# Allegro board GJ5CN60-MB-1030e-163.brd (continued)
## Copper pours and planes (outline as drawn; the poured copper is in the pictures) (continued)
NVVDD on TOP (solid shape): 83.1,104.32 83.16,104.41 83.27,104.39 83.4,104.26 83.87,104.26 83.87,103.95 83.72,103.8 83.72,103.76 83.64,103.68 83.64,103.38 83.72,103.31 83.72,103.28 83.75,103.21 83.92,103.04 83.92,102.62 83.75,102.46 83.72,102.38 83.72,102.36 83.62,102.25 83.62,102.01 83.72,101.91 83.72,101.88 83.75,101.81 83.89,101.66 83.89,101.22 83.75,101.08 83.74,101.04 83.72,100.98 83.68,100.93 83.64,100.9 83.64,100.83 83.63,100.78 83.63,100.73 83.6,100.66 83.53,100.63 83.42,100.6 83.33,100.52 83.29,100.51 83.21,100.5 83.16,100.48 83.1,100.48 83.1,100.54 83.06,100.57 82.98,100.71 82.98,100.87 83.05,100.93 83.1,101.03 83.1,101.89 83.06,101.92 82.97,102.13 83.06,102.34 83.1,102.37 83.1,103.29 83.06,103.32 82.97,103.53 83.06,103.74 83.1,103.77
NVVDD on TOP (solid shape): 83.1,104.32 83.16,104.41 83.27,104.39 83.4,104.26 83.87,104.26 83.87,103.95 83.72,103.8 83.72,103.76 83.64,103.68 83.64,103.38 83.72,103.31 83.72,103.28 83.75,103.21 83.92,103.04 83.92,102.62 83.75,102.46 83.72,102.38 83.72,102.36 83.62,102.25 83.62,102.01 83.72,101.91 83.72,101.88 83.75,101.81 83.89,101.66 83.89,101.22 83.75,101.08 83.74,101.04 83.72,100.98 83.68,100.93 83.64,100.9 83.64,100.83 83.63,100.78 83.63,100.73 83.6,100.66 83.53,100.63 83.42,100.6 83.33,100.52 83.29,100.51 83.21,100.5 83.16,100.48 83.1,100.48 83.1,100.54 83.06,100.57 82.98,100.71 82.98,100.87 83.05,100.93 83.1,101.03 83.1,101.89 83.06,101.92 82.97,102.13 83.06,102.34 83.1,102.37 83.1,103.29 83.06,103.32 82.97,103.53 83.06,103.74 83.1,103.77
NVVDD on TOP (solid shape): 83.1,104.32 83.16,104.41 83.27,104.39 83.4,104.26 83.87,104.26 83.87,103.95 83.72,103.8 83.72,103.76 83.64,103.68 83.64,103.38 83.72,103.31 83.72,103.28 83.75,103.21 83.92,103.04 83.92,102.62 83.75,102.46 83.72,102.38 83.72,102.36 83.62,102.25 83.62,102.01 83.72,101.91 83.72,101.88 83.75,101.81 83.89,101.66 83.89,101.22 83.75,101.08 83.74,101.04 83.72,100.98 83.68,100.93 83.64,100.9 83.64,100.83 83.63,100.78 83.63,100.73 83.6,100.66 83.53,100.63 83.42,100.6 83.33,100.52 83.29,100.51 83.21,100.5 83.16,100.48 83.1,100.48 83.1,100.54 83.06,100.57 82.98,100.71 82.98,100.87 83.05,100.93 83.1,101.03 83.1,101.89 83.06,101.92 82.97,102.13 83.06,102.34 83.1,102.37 83.1,103.29 83.06,103.32 82.97,103.53 83.06,103.74 83.1,103.77
NVVDD on TOP (solid shape): 73.36,104.3 73.41,104.31 73.44,104.26 73.44,103.8 73.49,103.76 73.62,103.53 73.49,103.3 73.44,103.27 73.44,102.4 73.49,102.36 73.62,102.13 73.49,101.9 73.44,101.87 73.44,101.09 73.5,101.04 73.5,101.02 73.54,100.93 73.62,100.86 73.62,100.78 73.62,100.65 73.47,100.5 73.34,100.5 73.3,100.51 73.26,100.52 73.17,100.6 73.05,100.63 73.01,100.65 73,100.68 73,100.85 72.93,100.92 72.88,100.97 72.77,101.07 72.77,101.76 72.87,101.86 72.87,101.9 72.9,101.94 72.96,102 73,102.07 73,102.19 72.96,102.26 72.9,102.32 72.87,102.36 72.87,102.38 72.84,102.48 72.8,102.52 72.8,103.16 72.84,103.21 72.87,103.28 72.87,103.3 72.92,103.36 72.93,103.39 72.96,103.53 72.93,103.68 72.92,103.7 72.87,103.76 72.87,103.8 72.77,103.9 72.77,104.24 73.3,104.24
NVVDD on TOP (solid shape): 86.01,96.76 86.09,96.76 86.13,96.74 86.22,96.67 86.33,96.63 86.39,96.6 86.42,96.53 86.42,96.39 86.49,96.32 86.51,96.29 86.59,96.21 86.59,95.45 86.52,95.38 86.52,95.36 86.42,95.25 86.42,95.01 86.52,94.9 86.52,94.88 86.54,94.75 86.54,94.11 86.55,94.07 86.54,94.03 86.52,93.98 86.52,93.96 86.49,93.92 86.42,93.85 86.42,93.61 86.49,93.54 86.52,93.51 86.52,93.46 86.57,93.41 86.57,92.99 86.2,92.99 86.07,92.86 85.96,92.84 85.9,92.93 85.9,93.5 85.86,93.53 85.77,93.73 85.86,93.94 85.9,93.97 85.9,94.9 85.86,94.93 85.77,95.13 85.86,95.34 85.9,95.37 85.9,96.24 85.88,96.26 85.84,96.34 85.78,96.39 85.78,96.55 85.86,96.69 85.9,96.72 85.9,96.78 85.96,96.78
NVVDD on TOP (solid shape): 86.01,96.76 86.09,96.76 86.13,96.74 86.22,96.67 86.33,96.63 86.39,96.6 86.42,96.54 86.42,96.39 86.49,96.32 86.51,96.29 86.59,96.21 86.59,95.45 86.52,95.38 86.52,95.36 86.42,95.25 86.42,95.01 86.52,94.9 86.52,94.88 86.54,94.75 86.54,94.11 86.55,94.1 86.55,94.07 86.54,94.03 86.52,93.98 86.52,93.96 86.42,93.85 86.42,93.61 86.52,93.5 86.52,93.46 86.57,93.41 86.57,92.99 86.2,92.99 86.07,92.86 85.96,92.84 85.9,92.93 85.9,93.5 85.86,93.53 85.77,93.73 85.86,93.94 85.9,93.97 85.9,94.9 85.86,94.93 85.77,95.13 85.86,95.34 85.9,95.37 85.9,96.24 85.88,96.26 85.84,96.34 85.78,96.39 85.78,96.55 85.86,96.69 85.9,96.72 85.9,96.78 85.96,96.78
NVVDD on TOP (solid shape): 73.36,104.3 73.41,104.31 73.44,104.26 73.44,103.8 73.49,103.76 73.62,103.53 73.49,103.3 73.44,103.27 73.44,102.4 73.49,102.36 73.62,102.13 73.49,101.9 73.44,101.87 73.44,101.09 73.5,101.04 73.5,101.02 73.54,100.93 73.62,100.86 73.62,100.78 73.62,100.65 73.47,100.5 73.34,100.5 73.3,100.51 73.26,100.52 73.17,100.6 73.05,100.63 73.01,100.65 73,100.68 73,100.85 72.93,100.92 72.88,100.97 72.77,101.07 72.77,101.76 72.87,101.86 72.87,101.9 72.96,102 73,102.07 73,102.19 72.96,102.26 72.87,102.36 72.87,102.38 72.84,102.48 72.8,102.52 72.8,103.16 72.84,103.21 72.87,103.28 72.87,103.3 72.92,103.36 72.93,103.39 72.96,103.53 72.93,103.68 72.92,103.7 72.87,103.76 72.87,103.8 72.77,103.9 72.77,104.24 73.3,104.24
NVVDD on TOP (solid shape): 73.36,104.3 73.41,104.31 73.44,104.26 73.44,103.8 73.49,103.76 73.62,103.53 73.49,103.3 73.44,103.27 73.44,102.4 73.49,102.36 73.62,102.13 73.49,101.9 73.44,101.87 73.44,101.09 73.5,101.04 73.5,101.02 73.54,100.93 73.62,100.86 73.62,100.78 73.62,100.65 73.47,100.5 73.34,100.5 73.3,100.51 73.26,100.52 73.17,100.6 73.05,100.63 73.01,100.65 73,100.68 73,100.85 72.93,100.92 72.88,100.97 72.77,101.07 72.77,101.76 72.87,101.86 72.87,101.9 72.96,102 73,102.07 73,102.19 72.96,102.26 72.87,102.36 72.87,102.38 72.84,102.48 72.8,102.52 72.8,103.16 72.84,103.21 72.87,103.28 72.87,103.3 72.92,103.36 72.93,103.39 72.96,103.53 72.93,103.68 72.92,103.7 72.87,103.76 72.87,103.8 72.77,103.9 72.77,104.24 73.3,104.24
NVVDD on TOP (solid shape): 83.21,96.76 83.29,96.76 83.33,96.74 83.42,96.67 83.53,96.63 83.59,96.6 83.62,96.54 83.62,96.39 83.69,96.32 83.71,96.29 83.79,96.21 83.79,95.45 83.72,95.38 83.72,95.36 83.62,95.25 83.62,95.01 83.72,94.9 83.72,94.88 83.74,94.75 83.74,94.11 83.75,94.1 83.75,94.07 83.72,93.98 83.72,93.96 83.62,93.85 83.62,93.61 83.72,93.5 83.72,93.46 83.77,93.41 83.77,93.01 83.41,93.01 83.27,92.87 83.16,92.85 83.1,92.94 83.1,93.5 83.06,93.53 82.97,93.73 83.06,93.94 83.1,93.97 83.1,94.9 83.06,94.93 82.97,95.13 83.06,95.34 83.1,95.37 83.1,96.24 83.08,96.26 83.04,96.34 82.98,96.39 82.98,96.55 83.06,96.69 83.1,96.72 83.1,96.78 83.16,96.78
NVVDD on TOP (solid shape): 83.21,96.76 83.29,96.76 83.33,96.74 83.42,96.67 83.53,96.63 83.59,96.6 83.62,96.53 83.62,96.39 83.69,96.32 83.71,96.29 83.79,96.21 83.79,95.45 83.72,95.38 83.72,95.36 83.62,95.25 83.62,95.01 83.72,94.9 83.72,94.88 83.74,94.75 83.74,94.11 83.75,94.1 83.75,94.07 83.72,93.98 83.72,93.96 83.62,93.85 83.62,93.61 83.72,93.5 83.72,93.46 83.77,93.41 83.77,93.01 83.41,93.01 83.27,92.87 83.16,92.85 83.1,92.94 83.1,93.5 83.06,93.53 82.97,93.73 83.06,93.94 83.1,93.97 83.1,94.9 83.06,94.93 82.97,95.13 83.06,95.34 83.1,95.37 83.1,96.24 83.08,96.26 83.04,96.34 82.98,96.39 82.98,96.55 83.06,96.69 83.1,96.72 83.1,96.78 83.16,96.78
NVVDD on TOP (solid shape): 86.01,96.76 86.09,96.76 86.13,96.74 86.22,96.67 86.33,96.63 86.39,96.6 86.42,96.53 86.42,96.39 86.49,96.32 86.51,96.29 86.59,96.21 86.59,95.45 86.52,95.38 86.52,95.36 86.42,95.25 86.42,95.01 86.52,94.9 86.52,94.88 86.54,94.75 86.54,94.11 86.55,94.07 86.54,94.03 86.52,93.98 86.52,93.96 86.42,93.85 86.42,93.61 86.52,93.51 86.52,93.46 86.57,93.41 86.57,92.99 86.2,92.99 86.07,92.86 85.96,92.84 85.9,92.93 85.9,93.5 85.86,93.53 85.77,93.73 85.86,93.94 85.9,93.97 85.9,94.9 85.86,94.93 85.77,95.13 85.86,95.34 85.9,95.37 85.9,96.24 85.88,96.26 85.84,96.34 85.78,96.39 85.78,96.55 85.86,96.69 85.9,96.72 85.9,96.78 85.96,96.78
NVVDD on TOP (solid shape): 76.16,104.29 76.21,104.3 76.24,104.25 76.24,103.8 76.29,103.76 76.42,103.53 76.29,103.3 76.24,103.27 76.24,102.4 76.29,102.36 76.42,102.13 76.29,101.9 76.24,101.87 76.24,101.05 76.3,101.01 76.31,100.99 76.35,100.92 76.41,100.87 76.41,100.69 76.29,100.55 76.22,100.5 76.14,100.5 76.1,100.51 76.06,100.52 75.97,100.6 75.85,100.63 75.81,100.65 75.8,100.68 75.8,100.85 75.73,100.92 75.68,100.97 75.57,101.07 75.57,101.76 75.67,101.86 75.67,101.9 75.7,101.94 75.76,102 75.8,102.07 75.8,102.19 75.76,102.26 75.7,102.32 75.67,102.36 75.67,102.38 75.64,102.48 75.6,102.52 75.6,103.16 75.64,103.21 75.67,103.28 75.67,103.3 75.72,103.36 75.73,103.39 75.76,103.53 75.73,103.68 75.72,103.7 75.67,103.76 75.67,103.8 75.57,103.9 75.57,104.24 76.11,104.24
NVVDD on TOP (solid shape): 76.16,104.29 76.21,104.3 76.24,104.25 76.24,103.8 76.29,103.76 76.42,103.53 76.29,103.3 76.24,103.27 76.24,102.4 76.29,102.36 76.42,102.13 76.29,101.9 76.24,101.87 76.24,101.05 76.3,101.01 76.31,100.99 76.35,100.92 76.41,100.87 76.41,100.69 76.29,100.55 76.22,100.5 76.14,100.5 76.1,100.51 76.06,100.52 75.97,100.6 75.85,100.63 75.81,100.65 75.8,100.68 75.8,100.85 75.73,100.92 75.68,100.97 75.57,101.07 75.57,101.76 75.67,101.86 75.67,101.9 75.76,102 75.8,102.07 75.8,102.19 75.76,102.26 75.7,102.32 75.67,102.36 75.67,102.38 75.64,102.48 75.6,102.52 75.6,103.16 75.64,103.21 75.67,103.28 75.67,103.3 75.72,103.36 75.73,103.39 75.76,103.53 75.73,103.68 75.72,103.7 75.67,103.76 75.67,103.8 75.57,103.9 75.57,104.24 76.11,104.24
NVVDD on TOP (solid shape): 76.16,104.29 76.21,104.3 76.24,104.25 76.24,103.8 76.29,103.76 76.42,103.53 76.29,103.3 76.24,103.27 76.24,102.4 76.29,102.36 76.42,102.13 76.29,101.9 76.24,101.87 76.24,101.05 76.3,101.01 76.31,100.99 76.35,100.92 76.41,100.87 76.41,100.69 76.29,100.55 76.22,100.5 76.14,100.5 76.1,100.51 76.06,100.52 75.97,100.6 75.85,100.63 75.81,100.65 75.8,100.68 75.8,100.85 75.73,100.92 75.68,100.97 75.57,101.07 75.57,101.76 75.67,101.86 75.67,101.9 75.7,101.94 75.76,102 75.8,102.07 75.8,102.19 75.76,102.26 75.67,102.36 75.67,102.38 75.64,102.48 75.6,102.52 75.6,103.16 75.64,103.21 75.67,103.28 75.67,103.3 75.72,103.36 75.73,103.39 75.76,103.53 75.73,103.68 75.72,103.7 75.67,103.76 75.67,103.8 75.57,103.9 75.57,104.24 76.11,104.24
NVVDD on TOP (solid shape): 70.56,104.46 70.61,104.47 70.64,104.42 70.64,103.8 70.69,103.76 70.82,103.53 70.69,103.3 70.64,103.27 70.64,102.4 70.69,102.36 70.82,102.13 70.69,101.9 70.64,101.87 70.64,101.05 70.7,101.01 70.71,100.99 70.75,100.92 70.81,100.87 70.81,100.69 70.69,100.55 70.61,100.5 70.52,100.51 70.49,100.51 70.46,100.52 70.37,100.6 70.25,100.63 70.21,100.65 70.2,100.68 70.2,100.85 70.13,100.91 70.08,100.96 69.97,101.07 69.97,101.76 70.07,101.86 70.07,101.9 70.1,101.94 70.16,102 70.2,102.07 70.2,102.19 70.16,102.26 70.07,102.36 70.07,102.38 70.04,102.48 70,102.52 70,103.16 70.04,103.21 70.07,103.28 70.07,103.3 70.12,103.36 70.13,103.39 70.16,103.53 70.13,103.68 70.12,103.7 70.07,103.76 70.07,103.8 69.97,103.9 69.97,104.26 70.46,104.26 70.54,104.34 70.54,104.44
NVVDD on TOP (solid shape): 85.9,104.23 85.96,104.32 86.07,104.3 86.13,104.24 86.55,104.24 86.58,104.27 86.64,104.28 86.67,104.24 86.67,103.95 86.52,103.8 86.52,103.76 86.44,103.68 86.44,103.63 86.44,103.62 86.43,103.53 86.44,103.44 86.44,103.43 86.44,103.38 86.52,103.31 86.52,103.28 86.55,103.21 86.72,103.04 86.72,102.62 86.55,102.46 86.52,102.38 86.52,102.36 86.42,102.25 86.42,102.01 86.52,101.91 86.52,101.88 86.55,101.81 86.69,101.66 86.69,101.22 86.55,101.08 86.52,100.98 86.48,100.93 86.44,100.9 86.44,100.83 86.43,100.78 86.43,100.73 86.4,100.66 86.33,100.63 86.22,100.6 86.13,100.52 86.09,100.51 86.01,100.5 85.96,100.48 85.9,100.48 85.9,100.54 85.86,100.57 85.78,100.71 85.78,100.87 85.85,100.93 85.9,101.03 85.9,101.89 85.86,101.92 85.77,102.13 85.86,102.34 85.9,102.37 85.9,103.29 85.86,103.32 85.77,103.53 85.86,103.74 85.9,103.77
NVVDD on TOP (solid shape): 85.9,104.23 85.96,104.32 86.07,104.3 86.13,104.24 86.55,104.24 86.58,104.27 86.64,104.28 86.67,104.24 86.67,103.95 86.52,103.8 86.52,103.76 86.44,103.68 86.43,103.53 86.44,103.38 86.52,103.31 86.52,103.28 86.55,103.21 86.72,103.04 86.72,102.62 86.55,102.46 86.52,102.38 86.52,102.36 86.42,102.25 86.42,102.01 86.52,101.91 86.52,101.88 86.55,101.81 86.69,101.66 86.69,101.22 86.55,101.08 86.52,100.98 86.48,100.93 86.44,100.9 86.44,100.83 86.43,100.78 86.43,100.73 86.4,100.66 86.33,100.63 86.22,100.6 86.13,100.52 86.09,100.51 86.01,100.5 85.96,100.48 85.9,100.48 85.9,100.54 85.86,100.57 85.78,100.71 85.78,100.87 85.85,100.93 85.9,101.03 85.9,101.89 85.86,101.92 85.77,102.13 85.86,102.34 85.9,102.37 85.9,103.29 85.86,103.32 85.77,103.53 85.86,103.74 85.9,103.77
NVVDD on TOP (solid shape): 85.9,104.23 85.96,104.32 86.07,104.3 86.13,104.24 86.55,104.24 86.58,104.27 86.64,104.28 86.67,104.24 86.67,103.95 86.52,103.8 86.52,103.76 86.44,103.68 86.43,103.53 86.44,103.38 86.52,103.31 86.52,103.28 86.55,103.21 86.72,103.04 86.72,102.62 86.55,102.46 86.52,102.38 86.52,102.36 86.42,102.25 86.42,102.01 86.52,101.91 86.52,101.88 86.55,101.81 86.69,101.66 86.69,101.22 86.55,101.08 86.52,100.98 86.48,100.93 86.44,100.9 86.44,100.83 86.43,100.78 86.43,100.73 86.4,100.66 86.33,100.63 86.22,100.6 86.13,100.52 86.09,100.51 86.01,100.5 85.96,100.48 85.9,100.48 85.9,100.54 85.86,100.57 85.78,100.71 85.78,100.87 85.85,100.93 85.9,101.03 85.9,101.89 85.86,101.92 85.77,102.13 85.86,102.34 85.9,102.37 85.9,103.29 85.86,103.32 85.77,103.53 85.86,103.74 85.9,103.77
NVVDD on TOP (solid shape): 70.56,104.46 70.61,104.47 70.64,104.42 70.64,103.8 70.69,103.76 70.82,103.53 70.69,103.3 70.64,103.27 70.64,102.4 70.69,102.36 70.82,102.13 70.69,101.9 70.64,101.87 70.64,101.05 70.7,101.01 70.71,100.99 70.75,100.92 70.81,100.87 70.81,100.69 70.69,100.55 70.61,100.5 70.52,100.51 70.49,100.51 70.46,100.52 70.37,100.6 70.25,100.63 70.21,100.65 70.2,100.68 70.2,100.85 70.13,100.91 70.08,100.96 69.97,101.07 69.97,101.76 70.07,101.86 70.07,101.9 70.16,102 70.2,102.07 70.2,102.19 70.16,102.26 70.07,102.36 70.07,102.38 70.04,102.48 70,102.52 70,103.16 70.04,103.21 70.07,103.28 70.07,103.3 70.12,103.36 70.13,103.39 70.16,103.53 70.13,103.68 70.12,103.7 70.07,103.76 70.07,103.8 69.97,103.9 69.97,104.26 70.46,104.26 70.54,104.34 70.54,104.44
NVVDD on TOP (solid shape): 76.24,96.78 76.24,96.75 76.29,96.72 76.41,96.58 76.41,96.39 76.35,96.34 76.31,96.27 76.3,96.25 76.24,96.22 76.24,95.37 76.28,95.34 76.32,95.3 76.36,95.22 76.37,95.21 76.37,95.13 76.37,95.05 76.36,95.04 76.32,94.96 76.27,94.92 76.22,94.87 76.22,94.69 76.28,94.65 76.33,94.59 76.37,94.49 76.36,94.34 76.28,94.22 76.24,94.19 76.24,93.97 76.28,93.94 76.37,93.73 76.28,93.52 76.24,93.49 76.24,93.24 76.39,93.09 76.39,92.97 76.32,92.9 76.19,93.02 75.68,93.02 75.66,93 75.6,92.99 75.57,93.04 75.57,93.36 75.65,93.44 75.69,93.51 75.73,93.55 75.77,93.58 75.77,93.89 75.73,93.92 75.69,93.95 75.65,94.02 75.5,94.17 75.5,94.66 75.64,94.81 75.68,94.9 75.73,94.95 75.77,94.98 75.77,95.29 75.73,95.32 75.68,95.36 75.64,95.46 75.57,95.52 75.57,96.11 75.64,96.18 75.65,96.22 75.68,96.3 75.75,96.36 75.8,96.39 75.8,96.58 75.81,96.61 75.85,96.63 75.97,96.66 76.06,96.74 76.14,96.76 76.18,96.8
NVVDD on TOP (solid shape): 76.24,96.78 76.24,96.75 76.29,96.72 76.41,96.58 76.41,96.39 76.35,96.34 76.31,96.27 76.3,96.25 76.24,96.22 76.24,95.37 76.28,95.34 76.32,95.3 76.36,95.22 76.37,95.21 76.37,95.13 76.37,95.05 76.36,95.04 76.32,94.96 76.27,94.92 76.22,94.87 76.22,94.69 76.28,94.65 76.33,94.59 76.37,94.49 76.36,94.34 76.28,94.22 76.24,94.19 76.24,93.97 76.28,93.94 76.37,93.73 76.28,93.52 76.24,93.49 76.24,93.24 76.39,93.09 76.39,92.97 76.32,92.9 76.19,93.02 75.68,93.02 75.66,93 75.6,92.99 75.57,93.04 75.57,93.36 75.65,93.44 75.69,93.51 75.73,93.55 75.77,93.58 75.77,93.89 75.73,93.92 75.69,93.95 75.65,94.02 75.5,94.17 75.5,94.66 75.64,94.81 75.68,94.9 75.73,94.95 75.77,94.98 75.77,95.29 75.73,95.32 75.68,95.36 75.64,95.46 75.57,95.52 75.57,96.11 75.64,96.18 75.65,96.22 75.68,96.3 75.75,96.36 75.8,96.39 75.8,96.58 75.81,96.61 75.85,96.63 75.97,96.66 76.06,96.74 76.14,96.76 76.18,96.8
NVVDD on TOP (solid shape): 76.24,96.78 76.24,96.75 76.29,96.72 76.34,96.68 76.38,96.63 76.42,96.51 76.41,96.39 76.35,96.34 76.31,96.27 76.3,96.25 76.24,96.22 76.24,95.37 76.28,95.34 76.32,95.3 76.36,95.22 76.37,95.21 76.37,95.13 76.37,95.05 76.36,95.04 76.32,94.96 76.27,94.92 76.22,94.87 76.22,94.69 76.28,94.65 76.33,94.59 76.37,94.49 76.36,94.34 76.28,94.22 76.24,94.19 76.24,93.97 76.28,93.94 76.37,93.73 76.28,93.52 76.24,93.49 76.24,93.24 76.39,93.09 76.39,92.97 76.32,92.9 76.19,93.02 75.68,93.02 75.66,93 75.6,92.99 75.57,93.04 75.57,93.36 75.65,93.44 75.69,93.51 75.73,93.55 75.77,93.58 75.77,93.89 75.73,93.92 75.69,93.95 75.65,94.02 75.5,94.17 75.5,94.66 75.64,94.81 75.68,94.9 75.73,94.95 75.77,94.98 75.77,95.29 75.73,95.32 75.68,95.36 75.64,95.46 75.57,95.52 75.57,96.11 75.64,96.18 75.65,96.22 75.68,96.3 75.75,96.36 75.8,96.39 75.8,96.58 75.81,96.61 75.85,96.63 75.97,96.66 76.06,96.74 76.14,96.76 76.18,96.8
NVVDD on BOTTOM (solid shape): 41.6,150.37 41.6,131.19 40.01,129.59 32.23,129.59 30.68,131.14 30.68,150.85 31.57,151.74 40.23,151.74
NVVDD on L6_IN2 (solid shape): 44.12,157.66 44.12,151.31 41.99,149.18 41.99,133.07 41.22,132.31 30.63,132.31 29.82,133.12 29.82,153.24 30.55,153.24 30.56,153.19 30.57,153.13 30.59,153.08 30.62,153.03 30.65,152.99 30.69,152.95 30.74,152.91 30.79,152.89 30.84,152.87 30.89,152.86 30.95,152.86 31.01,152.87 31.06,152.88 31.11,152.9 31.16,152.93 31.2,152.97 31.24,153.01 31.27,153.05 31.29,153.1 31.31,153.16 31.32,153.21 31.32,153.27 31.31,153.32 31.29,153.38 31.27,153.43 31.24,153.47 31.2,153.52 31.16,153.55 31.11,153.58 31.06,153.6 31.01,153.62 30.95,153.62 30.89,153.62 30.84,153.61 30.79,153.59 30.74,153.57 30.69,153.54 30.65,153.5 30.62,153.45 30.59,153.4 30.57,153.35 30.56,153.3 30.55,153.24 29.82,153.24 29.82,154.49 33.55,158.22 43.56,158.22
NVVDD on TOP: outline of 282 points within 25.35,88.54 113.23,158.96
NVVDD on BOTTOM: 86.38,96.68 86.38,96.4 86.66,96.12 86.66,95.58 86.38,95.3 86.38,95 86.66,94.72 86.66,94.19 86.38,93.91 86.38,93.6 86.66,93.32 86.66,92.76 86.6,92.7 86.14,92.7 85.93,92.92 85.93,93.42 85.83,93.53 85.83,96.68 85.93,96.78 86.28,96.78
NVVDD on BOTTOM: 70.2,100.71 70.2,100.92 70,101.12 70,101.76 70.2,101.96 70.2,103.56 69.93,103.84 69.93,104.47 69.95,104.5 70.56,104.5 70.69,104.37 70.69,103.84 70.81,103.71 70.81,103.33 70.69,103.2 70.69,102.5 70.84,102.34 70.84,102.06 70.69,101.91 70.69,101.17 70.84,101.02 70.84,100.64 70.71,100.51 70.41,100.51
NVVDD on BOTTOM: 76.28,100.41 75.89,100.41 75.64,100.66 75.64,104.47 75.77,104.6 76.28,104.6 76.4,104.47 76.4,100.54
NVVDD on BOTTOM: 77.16,106.99 77.35,107.18 77.35,107.28 77.98,107.28 78.06,107.23 78.07,107.14 78.06,106.99 78.12,106.85 78.12,106.51 78.12,106.5 78.08,106.29 78.18,106.11 78.19,106.1 78.19,105.98 78.14,105.98 78.14,105.87 77.95,105.87 77.95,105.98 77.25,105.98 77.25,106.29 77.16,106.37 77.16,106.39 77.14,106.46 77.1,106.53 77.1,106.84 77.14,106.9
NVVDD on BOTTOM: 84.45,97.54 84.78,97.54 85.04,97.28 85.04,90.63 84.91,90.5 84.91,89.36 84.78,89.23 84.4,89.23 84.28,89.36 84.28,90.88 84.66,91.27 84.66,92.03 84.4,92.28 84.4,97.49
NVVDD on BOTTOM: 68.14,103.08 68.65,103.08 68.77,102.96 68.77,102.45 68.87,102.35 69.23,102.35 69.36,102.22 69.36,102.07 69.23,101.94 68.79,101.94 68.66,101.81 68.66,101.32 68.54,101.21 68.06,101.21 68.05,101.22 68.05,102.99
NVVDD on BOTTOM: outline of 392 points within 70.05,89.11 108.61,130.56 ; 2 cut-outs
NVVDD on L2_GND1: 99.75,24.84 97.74,26.85 97.74,32.49 99.14,33.88 99.14,40.82 97.84,42.12 88.06,42.12 87.32,42.86 87.32,53.82 88.85,55.35 88.85,64.83 84.89,68.79 55.04,68.79 53.54,70.29 53.54,72.62 67.39,86.46 67.39,87.99 68.15,88.75 68.15,107.67 69.4,108.92 83.49,108.92 94.31,119.74 94.31,121.47 93.04,122.74 93.04,129.77 96.72,133.45 96.72,145.6 96.07,146.26 95.18,146.26 93.14,148.29 52.76,148.29 52,149.05 46.2,149.05 43.26,146.11 43.26,132.65 42.64,132.03 32.18,132.03 31.57,132.65 31.57,153.77 38.28,160.48 40.44,160.48 45.16,165.2 45.16,170.03 45.65,170.51 75.03,170.51 77.55,168 77.55,164.95 79.22,163.27 99.28,163.27 112.34,150.22 112.34,134.85 115.79,131.4 118.08,131.4 119.1,130.38 123.16,130.38 126.06,127.48 126.06,121.47 119.84,115.25 119.84,110.8 115.14,106.1 115.14,103.94 112.72,101.53 112.72,87.81 111.2,86.29 111.2,84.18 112.47,82.91 112.47,62.33 116.28,58.52 116.28,32.82 113.99,30.54 113.99,28.38 110.46,24.84
NVVDD on L3_IN1: outline of 163 points within 33.6,104.65 106.1,155.71
NVVDD on L4_VCC1: outline of 85 points within 32.21,24.84 126.06,170.64 ; 2 cut-outs
NVVDD on L5_VCC2: 72.19,67.39 69.52,70.06 53.77,70.06 52.27,71.56 52.27,77.83 55.04,80.6 61.65,80.6 67.26,86.21 67.26,108.43 68.76,109.93 70.31,109.93 70.31,109.39 70.41,109.29 71.34,109.29 71.65,109.61 71.65,109.93 80.85,109.93 80.85,109.28 81.03,109.1 81.72,109.1 81.89,109.27 81.89,109.93 86.54,109.93 95.71,119.1 95.71,145.09 94.03,146.76 48.36,146.76 45.16,143.57 45.16,128.58 43.28,126.7 36.12,126.7 27.13,135.69 27.13,152.46 27.04,152.55 27.54,153.05 27.54,153.12 27.52,153.14 26.45,153.14 25.48,154.11 25.48,162.79 33.33,170.64 76.68,170.64 80.16,167.16 90.55,167.16 90.83,166.88 90.83,159.13 92.17,157.79 99.82,157.79 106.5,151.1 106.5,147.24 110.69,143.05 110.69,113.47 106.63,109.4 106.63,96.96 95.35,85.68 90.27,85.68 88.34,83.75 88.34,75.42 80.31,67.39
NVVDD on L8_IN3: outline of 127 points within 32.71,88.52 104.09,153.11 ; 3 cut-outs
NVVDD_VIN on TOP (solid shape): 12.27,120.35 12.27,118.44 11.51,117.68 4.14,117.68 4.01,117.81 4.01,118.32 4.52,118.82 4.77,118.82 6.68,120.73 11.89,120.73
NVVDD_VIN on TOP (solid shape): outline of 197 points within 2.7,127.84 19.29,141.15
NVVDD_VIN on BOTTOM (solid shape): outline of 151 points within 3.43,129.52 18.44,140.69
NVVDD_VIN on TOP: 17.22,161.24 17.98,160.48 17.98,156.67 18.53,156.12 18.53,155.28 18.4,155.15 5.16,155.15 4.39,155.91 4.39,160.61 5.03,161.24
NVVDD_VIN on L5_VCC2: 1.47,117.68 1.47,140.18 5.54,144.25 5.54,148.27 1.73,152.08 1.73,160.5 3.86,162.64 24.71,162.64 24.97,162.38 24.97,153.9 26.62,152.25 26.62,135.48 35.72,126.38 28.65,119.31 28.65,117.68
NVVDD_VIN on L8_IN3: 5.79,160.86 14.3,160.86 17.86,157.31 17.86,122.38 13.16,117.68 4.52,117.68 4.27,117.94 4.27,118.44 6.43,120.6 6.43,125.43 4.01,127.84 4.01,139.53 4.65,140.16 6.55,140.16 8.2,141.81 8.2,144.61 7.57,145.24 7.57,151.34 4.77,154.13 4.77,159.85
NVVDDS on TOP (solid shape): 69.54,69.42 69.54,67.14 69.16,66.75 55.83,66.75 55.32,67.26 55.32,69.93 55.45,70.06 68.91,70.06
NVVDDS on TOP (solid shape): 70.65,92.9 70.57,92.82 70.57,91.87 70.67,91.77 70.67,91.57 70.57,91.47 70.57,90.47 70.69,90.34 70.69,90.2 70.59,90.1 70.59,89.98 70.26,89.64 70.06,89.64 69.97,89.73 69.97,89.76 70.22,90.02 70.22,90.42 70.08,90.57 70.08,90.62 70.22,90.77 70.22,91.15 70.05,91.32 70.05,91.97 70.22,92.14 70.22,92.55 70.03,92.75 70.03,92.94 70.11,93.02 70.53,93.02
NVVDDS on TOP (solid shape): 73.44,92.89 73.37,92.82 73.37,91.87 73.47,91.77 73.47,91.57 73.37,91.47 73.37,90.47 73.49,90.34 73.49,90.2 73.39,90.1 73.39,89.96 73.06,89.62 72.86,89.62 72.77,89.71 72.77,89.76 73.03,90.02 73.03,90.42 72.87,90.57 72.87,90.62 73.03,90.77 73.03,91.15 72.85,91.32 72.85,91.97 73.03,92.14 73.03,92.55 72.78,92.79 72.78,92.87 72.91,93 73.33,93
NVVDDS on TOP (solid shape): 76.21,92.86 76.17,92.82 76.17,91.87 76.27,91.77 76.27,91.57 76.17,91.47 76.17,90.47 76.29,90.34 76.29,90.2 76.19,90.1 76.19,89.86 75.88,89.54 75.68,89.54 75.59,89.63 75.59,89.78 75.83,90.02 75.83,90.42 75.67,90.57 75.67,90.62 75.83,90.77 75.83,91.15 75.65,91.32 75.65,91.97 75.83,92.14 75.83,92.55 75.62,92.75 75.62,92.82 75.73,92.92 76.15,92.92
NVVDDS on TOP (solid shape): 81,107.5 81,107.47 80.77,107.25 80.77,106.87 80.87,106.77 80.87,106.65 80.74,106.52 80.74,106.14 80.97,105.92 80.97,105.27 80.96,105.26 80.78,105.02 80.83,104.72 80.84,104.7 80.84,104.67 81.02,104.49 81.02,104.34 80.65,104.34 80.35,104.64 80.35,107.4 80.53,107.57 80.93,107.57
NVVDDS on TOP (solid shape): 83.8,107.52 83.8,107.47 83.57,107.25 83.57,106.87 83.67,106.77 83.67,106.65 83.54,106.52 83.54,106.14 83.77,105.92 83.77,105.27 83.76,105.26 83.58,105.02 83.63,104.72 83.64,104.7 83.64,104.67 83.82,104.49 83.82,104.36 83.45,104.36 83.15,104.66 83.15,107.42 83.33,107.59 83.73,107.59
NVVDDS on TOP (solid shape): 80.91,92.68 80.77,92.55 80.77,92.14 80.96,91.95 80.96,91.41 80.94,91.4 80.94,91.3 80.79,91.15 80.79,91.07 80.79,91.06 80.77,90.93 80.79,90.8 80.79,90.8 80.79,90.69 80.92,90.57 80.92,90.55 80.79,90.42 80.79,90.37 80.79,90.36 80.77,90.23 80.79,90.1 80.79,90.1 80.79,90.04 80.97,89.87 80.97,89.73 80.9,89.66 80.65,89.66 80.35,89.96 80.35,92.6 80.66,92.9 80.91,92.9
NVVDDS on TOP (solid shape): 83.71,92.68 83.57,92.55 83.57,92.14 83.76,91.95 83.76,91.41 83.74,91.4 83.74,91.3 83.59,91.15 83.59,91.07 83.59,91.06 83.57,90.93 83.59,90.8 83.59,90.8 83.59,90.69 83.72,90.57 83.72,90.55 83.59,90.42 83.59,90.37 83.59,90.36 83.57,90.23 83.59,90.1 83.59,90.1 83.59,90.04 83.77,89.87 83.77,89.74 83.7,89.67 83.45,89.67 83.15,89.97 83.15,92.61 83.46,92.91 83.71,92.91
NVVDDS on TOP (solid shape): 86.5,92.67 86.37,92.55 86.37,92.14 86.55,91.96 86.55,91.4 86.54,91.4 86.54,91.3 86.39,91.15 86.39,91.07 86.37,90.96 86.38,90.84 86.38,90.82 86.38,90.81 86.39,90.79 86.39,90.69 86.52,90.57 86.52,90.55 86.39,90.42 86.39,90.37 86.39,90.36 86.37,90.23 86.39,90.1 86.39,90.1 86.39,90.04 86.57,89.87 86.57,89.73 86.49,89.65 86.24,89.65 85.95,89.94 85.95,92.6 86.25,92.89 86.5,92.89
NVVDDS on TOP (solid shape): 86.78,107.94 86.82,107.88 86.88,107.83 86.9,107.81 86.9,107.74 86.86,107.74 86.37,107.25 86.37,106.87 86.47,106.77 86.47,106.65 86.34,106.52 86.34,106.14 86.57,105.92 86.57,105.27 86.56,105.26 86.38,105.02 86.43,104.72 86.44,104.7 86.44,104.67 86.61,104.5 86.61,104.44 86.51,104.34 86.18,104.34 85.95,104.57 85.95,106.65 85.99,106.68 85.99,107.76 86.2,107.97 86.76,107.97
NVVDDS on TOP (solid shape): 70.59,107.37 70.59,104.64 70.44,104.48 70.44,104.38 70.42,104.36 70.03,104.36 70.03,104.49 70.2,104.67 70.2,104.8 70.2,104.8 70.22,104.93 70.2,105.06 70.2,105.07 70.2,105.15 70,105.35 70,105.94 70.18,106.12 70.18,106.14 70.18,106.15 70.23,106.34 70.18,106.52 70.18,106.84 70.23,107.03 70.18,107.21 70.18,107.22 70.18,107.25 69.91,107.51 69.91,107.61 70.35,107.61
NVVDDS on TOP (solid shape): 73.39,107.39 73.39,104.58 73.28,104.46 73.28,104.36 73.26,104.34 72.87,104.34 72.83,104.38 72.83,104.49 73,104.67 73,104.8 73,104.8 73.02,104.93 73,105.06 73,105.07 73,105.15 72.8,105.35 72.8,105.94 72.97,106.12 72.97,106.14 72.98,106.15 73.03,106.34 72.97,106.52 72.97,106.84 73.03,107.03 72.98,107.21 72.97,107.22 72.97,107.25 72.75,107.47 72.75,107.59 73.19,107.59
NVVDDS on TOP (solid shape): 76.19,107.4 76.19,104.57 76.09,104.46 76.09,104.36 76.07,104.34 75.68,104.34 75.62,104.39 75.62,104.49 75.8,104.67 75.8,104.8 75.8,104.8 75.82,104.93 75.8,105.06 75.8,105.07 75.8,105.15 75.6,105.35 75.6,105.94 75.78,106.12 75.78,106.14 75.78,106.15 75.83,106.34 75.78,106.52 75.78,106.84 75.83,107.03 75.78,107.21 75.78,107.22 75.78,107.25 75.56,107.46 75.56,107.59 76,107.59
NVVDDS on TOP (solid shape): 80.48,100.94 80.58,100.83 80.72,100.78 80.75,100.76 80.77,100.73 80.77,100.67 80.79,100.6 80.79,100.17 80.79,100.16 80.77,100.03 80.79,99.9 80.79,99.9 80.79,99.79 80.94,99.65 80.94,98.99 80.74,98.8 80.74,98.47 80.94,98.27 80.94,97.59 80.77,97.42 80.77,96.6 80.77,96.56 80.68,96.48 80.67,96.48 80.58,96.43 80.5,96.36 80.35,96.36 80.35,100.96 80.46,100.96
NVVDDS on TOP (solid shape): 72.95,100.5 73.02,100.53 73.09,100.5 73.21,100.43 73.34,100.4 73.39,100.4 73.39,96.98 73.27,96.85 73.25,96.85 73.17,96.82 73.09,96.76 73.02,96.74 72.95,96.77 72.87,96.85 72.87,96.89 73.03,97.04 73.03,97.4 72.83,97.6 72.83,98.29 72.84,98.3 72.91,98.36 72.97,98.44 73,98.47 73,98.5 73.02,98.63 73,98.76 73,98.77 73,98.85 72.87,98.97 72.87,99.72 73.03,99.87 73.03,100.2 72.9,100.32 72.9,100.44
NVVDDS on TOP (solid shape): 70.15,100.5 70.22,100.53 70.29,100.5 70.39,100.44 70.51,100.4 70.53,100.4 70.59,100.34 70.59,96.95 70.5,96.86 70.49,96.86 70.38,96.82 70.29,96.76 70.22,96.74 70.15,96.77 70.08,96.85 70.08,96.89 70.22,97.04 70.22,97.4 70.03,97.6 70.03,98.29 70.04,98.3 70.11,98.36 70.17,98.44 70.2,98.47 70.2,98.5 70.22,98.63 70.2,98.76 70.2,98.77 70.2,98.85 70.08,98.97 70.08,99.72 70.22,99.87 70.22,100.2 70.1,100.32 70.1,100.44
NVVDDS on TOP (solid shape): 75.75,100.5 75.82,100.53 75.89,100.5 76.01,100.43 76.14,100.4 76.16,100.4 76.19,100.37 76.19,96.96 76.09,96.86 76.08,96.85 75.98,96.82 75.89,96.76 75.82,96.74 75.75,96.77 75.67,96.85 75.67,96.89 75.83,97.04 75.83,97.4 75.62,97.6 75.62,98.29 75.64,98.3 75.71,98.36 75.77,98.44 75.8,98.47 75.8,98.5 75.82,98.63 75.8,98.76 75.8,98.77 75.8,98.85 75.67,98.97 75.67,99.72 75.83,99.87 75.83,100.2 75.7,100.32 75.7,100.44
NVVDDS on TOP (solid shape): 78.88,107.52 78.88,107.37 78.67,107.07 78.81,106.74 78.83,106.72 78.83,106.64 78.81,106.63 78.68,106.43 78.69,106.19 78.7,106.17 78.77,106.07 78.87,106 78.9,105.98 78.9,105.28 78.87,105.27 78.67,104.91 78.91,104.58 78.94,104.57 78.94,104.38 78.92,104.36 78.53,104.36 78.32,104.56 78.32,104.7 78.18,104.85 78.18,105.02 78.3,105.14 78.3,107.49 78.41,107.59 78.81,107.59
NVVDDS on TOP (solid shape): 78.34,92.92 78.29,92.87 78.29,92.47 78.37,92.39 78.37,92.27 78.29,92.2 78.29,91.77 78.39,91.67 78.39,91.57 78.27,91.45 78.27,91.09 78.37,90.99 78.37,90.85 78.29,90.77 78.29,90.39 78.42,90.27 78.42,90.2 78.24,90.02 78.24,89.86 78,89.61 77.8,89.61 77.71,89.7 77.71,89.89 77.92,90.17 77.81,90.51 77.77,90.58 77.81,90.65 77.92,90.97 77.75,91.25 77.75,92.01 77.92,92.35 77.72,92.67 77.72,92.86 77.85,92.99 78.27,92.99
NVVDDS on TOP (solid shape): outline of 314 points within 20.01,65.76 40.64,82.16
NVVDDS on BOTTOM: 30.23,70.25 40.54,70.25 40.74,70.05 40.74,66.75 41,66.5 47.19,66.5 49.86,69.17 69.54,69.17 70.05,68.66 70.05,67.14 69.67,66.75 63.96,66.75 62.69,65.48 57.23,65.48 55.57,63.83 47.83,63.83 47.07,64.6 32.1,64.6 29.88,66.82 29.88,69.89
NVVDDS on L3_IN1: outline of 237 points within 19.67,58.58 89.58,108.06 ; 2 cut-outs
NVVDDS on L4_VCC1: 22.91,50.37 19.89,53.4 19.89,82.02 20.37,82.5 28.16,82.5 29.03,81.64 29.03,73.51 30.83,71.71 38.96,71.71 41.12,69.55 50.47,69.55 67.39,86.46 67.39,97.62 86.84,97.62 87.45,97 87.45,96.75 87.54,96.66 87.45,96.58 87.45,76.13 61.69,50.37 ; 1 cut-out
NVVDDS on L5_VCC2: 48.14,63.87 46.03,65.99 34.9,65.99 33.63,64.72 27.8,64.72 27.13,65.4 27.13,71.35 28.9,73.13 30.83,71.2 51.91,71.2 53.56,69.55 69.31,69.55 71.7,67.16 71.7,66.12 50.39,66.12
NVVDDS on L6_IN2: outline of 233 points within 19.51,53.55 87.44,108.73 ; 2 cut-outs
NVVDDS_VIN on TOP (solid shape): 4.25,62.42 4.25,58.99 4.01,58.75 1.73,58.75 1.22,59.26 1.22,62.86 1.57,63.22 3.45,63.22
NVVDDS_VIN on TOP (solid shape): 9.47,81.36 9.47,80.34 9.85,79.96 10.24,79.96 10.74,79.45 10.74,78.92 10.67,78.84 2.68,78.84 2.35,79.18 2.35,81.62 2.57,81.84 8.99,81.84
NVVDDS_VIN on BOTTOM: 7.59,81.84 7.95,81.49 7.95,79.58 7.82,79.45 5.66,79.45 3.5,77.3 3.5,73.99 4.27,73.23 4.27,60.53 2.87,59.13 1.35,59.13 1.09,59.39 1.09,77.93 2.37,79.21 2.37,81.62 2.59,81.84
NVVDDS_VIN on L6_IN2: 1.98,81.87 6.43,81.87 7.19,81.11 7.19,64.85 4.9,62.56 4.9,59.64 3.76,58.5 1.98,58.5 1.22,59.26 1.22,81.11
PEX_VCC_LX on TOP (solid shape): 90.75,61.8 90.75,61.29 90.37,60.91 89.61,60.91 88.72,60.02 88.72,59.01 88.4,58.69 87.13,58.69 86.82,58.37 85.29,58.37 85.17,58.5 85.17,61.52 85.67,62.02 90.53,62.02
PEX_VDD on TOP (solid shape): 86.94,74.56 86.94,70.69 88.88,68.75 89.39,68.75 89.48,68.66 89.48,66.75 89.1,66.37 89.1,64.47 88.34,63.71 84.91,63.71 84.4,64.21 84.4,65.48 84.28,65.61 83.53,65.61 83.41,65.73 83.41,68.68 83.47,68.74 83.47,74.39 83.9,74.82 86.68,74.82
PEX_VDD on TOP (solid shape): 90.58,105.69 90.58,105.66 90.59,105.44 90.73,105.27 90.73,105.1 90.51,104.88 90.49,104.88 90.37,104.83 90.28,104.73 90.28,104.72 90.1,104.63 89.93,104.49 89.87,104.28 89.84,104.21 89.79,104.18 89.71,104.15 89.65,104.11 89.49,104.11 89.37,104.19 88.77,103.88 89.37,103.58 89.49,103.65 89.65,103.65 89.92,103.59 90.13,103.78 90.21,103.85 90.3,103.82 90.57,103.55 90.57,103.52 90.59,103.36 90.67,103.22 90.7,103.15 90.67,103.08 90.61,103.01 88.67,103.01 88.56,103.12 88.56,105.67 88.67,105.79 88.76,105.82 88.83,105.77 89.08,105.61 89.37,105.68 89.49,105.75 89.65,105.75 89.94,105.69 90.14,105.9 90.15,105.94 90.33,105.94
PEX_VDD on TOP (solid shape): 90.02,96.34 90.02,96.18 89.91,96.05 89.87,95.88 89.84,95.81 89.79,95.78 89.71,95.75 89.65,95.71 89.49,95.71 89.37,95.79 88.77,95.48 89.37,95.17 89.49,95.25 89.65,95.25 89.71,95.21 89.79,95.18 89.84,95.15 89.87,95.08 89.91,94.92 90.02,94.78 90.02,94.08 89.91,93.95 89.87,93.78 89.84,93.71 89.79,93.68 89.71,93.65 89.65,93.61 89.49,93.61 89.37,93.69 88.77,93.38 89.37,93.07 89.49,93.15 89.65,93.15 89.71,93.11 89.79,93.08 89.84,93.05 89.87,92.98 89.91,92.82 90.02,92.68 90.02,91.98 89.91,91.85 89.87,91.68 89.84,91.61 89.79,91.58 89.71,91.55 89.65,91.51 89.49,91.51 89.37,91.59 88.77,91.28 89.37,90.97 89.49,91.05 89.65,91.05 89.71,91.01 89.79,90.98 89.84,90.95 89.87,90.88 89.91,90.72 90.02,90.58 90.02,90.47 89.83,90.28 88.62,90.28 88.55,90.35 88.55,96.23 88.89,96.57 89.79,96.57
PEX_VDD on BOTTOM (solid shape): outline of 90 points within 87.93,102.55 90.56,105.89
PEX_VDD on BOTTOM: 87.85,91.24 88.16,91.55 88.16,92.26 87.85,92.57 87.85,96.08 87.94,96.16 88.54,96.16 89.55,97.17 96.45,97.17 96.51,97.12 96.51,96.56 97.09,95.97 97.09,92.15 100.28,88.97 100.28,77.42 96.47,73.61 83.77,73.61 83.39,73.99 83.39,78.57 84.53,79.71 93.8,79.71 96.47,82.38 96.47,87.81 93.67,90.6 89.18,90.6 88.54,89.97 87.98,89.97 87.85,90.11
PEX_VDD on L3_IN1: 88.1,90.18 88.1,104.11 88.59,104.6 95.71,104.6 96.64,103.67 96.64,91.02 95.39,89.78 88.51,89.78 ; 2 cut-outs
PH1_NVD on TOP (solid shape): 23.22,131.43 23.22,122.66 22.64,122.08 20.52,122.08 20.41,122.19 20.41,124.05 19.37,125.08 8.26,125.08 8.12,125.23 8.12,127.83 8.26,127.98 19.28,127.98 19.58,128.28 19.58,129.16 19.21,129.53 19.21,131.56 19.31,131.66 22.98,131.66
PH2_NVD on TOP (solid shape): outline of 140 points within 8.17,137.18 24.12,147.15
PH3_NVD on TOP (solid shape): 23.36,158.91 23.36,151.76 22.94,151.34 21.16,151.34 20.53,151.96 8.19,151.96 7.97,152.18 7.97,154.77 8.04,154.85 19.75,154.85 20.12,155.21 20.12,158.89 20.31,159.08 23.19,159.08
PHASE_GCORE1 on TOP (solid shape): 18.18,81.56 18.18,75.01 17.81,74.64 16.04,74.64 15.89,74.79 15.89,75.52 15.69,75.72 5.77,75.72 5.61,75.87 5.61,78.36 5.92,78.67 10.84,78.67 11.45,79.28 12.09,79.28 12.27,79.45 12.27,81.38 12.62,81.74 18,81.74
REGOUT_LAN on TOP: 95.96,49.86 97.23,49.86 97.74,49.36 100.02,49.36 100.66,48.72 102.82,48.72 103.07,48.47 103.07,47.7 102.82,47.45 98.25,47.45 97.48,48.21 96.98,48.21 96.34,48.85 95.93,48.85 95.73,49.05 95.73,49.89 95.76,49.91 95.91,49.91
RT8237E_LX_GDDR on TOP (solid shape): 18.63,87.58 18.63,84.17 17.86,83.39 15.32,83.39 14.81,83.9 14.81,84.73 14.43,85.11 13.07,85.11 12.64,85.54 1.59,85.54 1.25,85.87 1.25,88.08 1.57,88.39 13.01,88.39 13.19,88.57 17.64,88.57
S_GND_R on BOTTOM (solid shape): 10.49,50.37 10.49,49.86 10.36,49.74 8.58,49.74 8.46,49.86 8.46,50.37 8.58,50.5 10.36,50.5
SW1_VRA on TOP (solid shape): 131.09,156.62 131.09,154.71 131.24,154.56 132.26,154.56 132.38,154.44 132.38,150.09 132.16,149.86 126.69,149.86 126.44,150.12 126.44,152.99 126.95,153.5 128.85,153.5 128.98,153.62 128.98,154.54 129.21,154.77 129.21,156.59 129.28,156.67 131.04,156.67
SW2_GT on TOP (solid shape): 157,151.01 157,149.28 157.17,149.11 158.93,149.11 159.15,148.89 159.15,145.64 158.65,145.14 151.76,145.14 151,145.9 151,147.58 151.59,148.16 154.76,148.16 154.9,148.3 154.9,149.04 155.09,149.23 155.09,151.05 155.13,151.1 156.91,151.1
SW2_VRA on TOP (solid shape): 138.53,156.09 138.53,154.38 138.68,154.23 139.39,154.23 139.55,154.08 139.55,150.17 139.24,149.86 134.14,149.86 133.99,150.01 133.99,152.61 134.5,153.11 135.97,153.11 136.35,153.5 136.35,154.03 136.57,154.26 136.57,156.14 136.63,156.19 138.43,156.19
SW3_VRA on TOP (solid shape): 146.66,156.44 146.66,154.56 146.89,154.33 147.78,154.33 147.9,154.21 147.9,149.69 147.42,149.2 141.58,149.2 141.32,149.46 141.32,152.89 141.81,153.37 144.35,153.37 144.5,153.52 144.5,154.36 144.7,154.56 144.7,156.49 144.75,156.54 146.56,156.54
SW4_VRA on TOP (solid shape): 122.91,156.49 122.91,154.79 123.01,154.69 124.66,154.69 124.75,154.59 124.75,150 124.06,149.3 117.68,149.3 117.42,149.56 117.42,153.24 117.8,153.62 120.6,153.62 120.73,153.75 120.73,154.39 120.97,154.64 120.97,156.56 121,156.59 122.81,156.59
SW_1.2VS on TOP (solid shape): 184.43,110.16 184.43,109.05 184.56,108.92 186.59,108.92 186.62,108.9 186.62,108.63 186.57,108.58 184.18,108.58 184.05,108.46 184.05,106.55 182.78,105.27 182.78,104.6 182.55,104.37 181.95,104.37 180.39,105.93 180.39,110.09 180.81,110.51 184.08,110.51
SW_SA on TOP (solid shape): 165.83,151.02 165.83,149.36 166.32,148.87 167.37,148.87 167.47,148.77 167.47,148.03 167.63,147.88 169.28,147.88 169.67,147.5 169.67,144.91 169.37,144.61 161.46,144.61 160.95,145.11 160.95,147.62 161.49,148.16 163.52,148.16 163.68,148.31 163.68,149.03 163.95,149.3 163.95,151.05 163.96,151.06 165.79,151.06
TON_VCCIO on TOP (solid shape): 97.19,161.5 97.51,161.5 97.52,161.5 98.06,161.5 98.17,161.39 98.17,160.74 98.1,160.67 96.19,160.67 96.09,160.77 96.09,161.56 96.16,161.63 97.05,161.63
USB0_5V on TOP (solid shape): 128.26,175.41 128.26,174.77 127.56,174.06 126.89,174.06 126.67,173.84 126.67,173.27 126.45,173.05 125.78,173.05 125.62,172.89 125.62,169.53 125.49,169.4 125.31,169.4 125.3,169.41 125.14,169.45 124.99,169.41 124.98,169.4 124.76,169.4 124.74,169.41 124.59,169.45 124.43,169.41 124.42,169.4 124.2,169.4 124.19,169.41 124.03,169.45 123.87,169.41 123.86,169.4 122.03,169.4 121.94,169.49 121.94,173.72 122.35,174.13 125.01,174.13 126.56,175.67 128,175.67
USB0_5V on BOTTOM: 126.88,175.73 128.72,175.73 129.15,175.3 129.15,171.3 129.08,171.23 123.46,171.23 123.41,171.29 123.41,172.25
USB1_5V on TOP (solid shape): 108.12,175.25 108.12,174.46 108.11,174.46 108.11,172.97 108.28,172.81 108.28,168.06 109.21,167.13 109.21,165.31 108.83,164.92 106.64,164.92 106.5,165.07 106.5,172.29 106.25,172.55 106.25,175.34 106.5,175.59 107.77,175.59
USB1_5V on BOTTOM (solid shape): 108.79,175.34 108.79,174.36 108.66,174.09 108.79,173.83 108.79,173.69 109.55,172.93 109.55,167.21 109.04,166.7 107.01,166.7 106.63,167.08 106.63,175.34 107.01,175.72 108.41,175.72
VAD_BATT on TOP: 12.27,52.53 15.95,52.53 16.59,51.9 16.59,48.59 16.2,48.21 12.52,48.21 12.01,48.72 12.01,52.28
VCHG on TOP: 20.9,45.55 26.11,45.55 27,44.66 27,39.27 26.31,38.59 20.62,38.59 20.01,39.2 20.01,44.66
VCHG_OUT on TOP: 44.53,50.12 37.79,50.12 37.41,50.5 37.41,52.66 38.18,53.42 41.22,53.42 41.73,53.93 41.73,56.34 42.11,56.72 44.4,56.72 44.78,56.34 44.78,50.37
VCHG_OUT on TOP: 12.9,45.16 18.49,45.16 18.81,44.85 18.81,39.26 18.24,38.69 14.05,38.69 12.65,40.08 12.65,44.91
VCHG_OUT on BOTTOM: 38.94,55.45 44.4,55.45 44.78,55.07 44.78,50.75 44.65,50.63 38.81,50.63 38.18,51.26 38.18,54.69
VCHG_OUT on L3_IN1: 34.75,56.47 45.92,56.47 46.43,55.96 46.43,45.67 38.56,37.8 13.16,37.8 11.63,39.32 11.63,48.09 14.55,51.01 29.29,51.01
VRA_GND on TOP (solid shape): 190.83,151.59 190.83,150.07 190.7,149.94 188.92,149.94 188.8,150.07 188.8,151.08 189.43,151.72 190.7,151.72
VRA_GND on TOP: 182.3,149.05 186.64,149.05 186.77,148.92 186.77,144.6 186.68,144.51 182.29,144.51 182.18,144.62 182.18,148.93
VRA_GND on L2_GND1: 181.41,138.69 175.84,144.25 175.84,152.02 176.94,153.11 189.63,153.11 191.49,151.26 191.49,140.72 189.45,138.69
WEBCAM_+5V on TOP (solid shape): 78.48,158.58 80.72,158.58 81.1,158.19 81.1,157.05 80.85,156.8 79.83,156.8 79.58,157.05 79.58,157.31 79.45,157.43 78.48,157.43 78.33,157.28 76.41,157.28 76.36,157.3 76.18,157.48 76.18,158.64 76.38,158.84 78.22,158.84
WLAN_3.3VDD on TOP (solid shape): 99.39,10.11 99.39,7.13 99.26,7 97.7,7 97.56,7.14 97.56,10.12 97.88,10.44 99.06,10.44
WLAN_3.3VDD on TOP (solid shape): 80.89,8.6 80.92,8.56 80.98,8.05 81.5,8.06 81.8,8.06 81.91,7.95 81.91,6.86 81.75,6.7 79.36,6.7 79.07,6.99 79.07,9.98 79.37,10.29 80.89,10.29
WLAN_3.3VDD on BOTTOM: 96.96,7.07 96.96,9.09 98.62,10.75 98.63,10.75 99.9,10.75 100.15,10.49 100.15,8.08 100.91,7.32 100.91,6.05 100.53,5.67 98.37,5.67
WLAN_3.3VDD on L3_IN1: 81.36,6.81 81.36,7.97 81.39,7.99 81.56,8.15 81.61,8.39 98.88,8.39 99.39,7.88 99.39,6.48 98.75,5.85 82.32,5.85
N888421 on TOP (solid shape): 66.84,164.95 66.84,163.92 66.65,163.73 63.67,163.73 62.85,162.91 61.62,162.91 61.44,163.08 61.44,164 61.6,164.15 62.28,164.15 63.21,165.08 66.71,165.08
N2051160 on BOTTOM (solid shape): 44.18,163.32 44.18,162.33 43.55,161.69 43.55,160.38 43.31,160.15 42.34,160.15 42,160.49 42,163.35 42.04,163.38 44.12,163.38
N22554790 on TOP (solid shape): 163.21,150.09 163.21,149.34 163.4,149.15 163.4,148.42 163.36,148.38 162.55,148.38 162.25,148.67 162.25,150.07 162.35,150.16 163.14,150.16
N26148392 on L8_IN3 (solid shape): outline of 1136 points within 137.84,111.19 157.25,113.82
N26195158 on BOTTOM: 180.9,74.78 183.31,74.78 185.16,72.93 185.16,71.83 185.14,71.81 184.05,71.81 183.92,71.94 183.92,72.93 183.51,73.33 180.92,73.33 180.64,73.61 180.64,74.53
N26377234 on TOP (solid shape): 80.22,61.47 80.22,60.21 79.57,59.56 79.57,58.3 79.49,58.21 78.38,58.21 78.04,58.56 78.04,61.46 78.12,61.54 80.15,61.54
N27587554 on TOP (solid shape): 143.94,155.55 143.94,154.64 144.22,154.36 144.22,153.75 144.09,153.62 143.2,153.62 143.07,153.76 143.07,155.54 143.14,155.6 143.89,155.6
N27591037 on TOP (solid shape): 128.44,155.72 128.44,154.77 128.73,154.47 128.73,153.88 128.6,153.75 127.84,153.75 127.56,154.03 127.56,155.7 127.61,155.75 128.41,155.75
N27607656 on TOP (solid shape): 135.81,155.2 135.81,154.38 136.09,154.1 136.09,153.5 135.97,153.37 135.2,153.37 134.9,153.67 134.9,155.19 134.96,155.25 135.76,155.25
N27607947 on TOP (solid shape): 120.19,155.63 120.19,154.79 120.47,154.51 120.47,153.93 120.42,153.88 119.43,153.88 119.28,154.03 119.28,155.58 119.35,155.65 120.17,155.65
N27609681 on TOP (solid shape): 154.25,150.13 154.25,149.3 154.63,148.92 154.63,148.42 154.56,148.34 153.69,148.34 153.36,148.67 153.36,150.06 153.49,150.19 154.2,150.19

Small or netless copper shapes (teardrops, artwork), in the pictures only: 97 on TOP, 4 on BOTTOM, 3 on L8_IN3

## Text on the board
Ref Des/Silkscreen Bottom: 1 | A
User.Comments: GJ5KN6A MB V1.1 | 2017 / 07 / 21
Ref Des/Silkscreen Top: B | c | 1 | A | D | E | G | F | GJ5KN6A MB V1.1
L2_GND1: LAYER2:GND1
L3_IN1: LAYER3:IN1
L4_VCC1: LAYER4:VCC1
L5_VCC2: LAYER5:VCC2
L6_IN2: LAYER6:IN2
L7_GND2: LAYER7:GND2
L8_IN3: LAYER8:IN3
L9_GND3: LAYER9 :GND3
User.20: FIGURE | SIZE | 10.0 | 20.0 | 28.0 | 35.43 | 39.0 | 55.0 | 71.0 | 79.0 | 110.0 | 118.0 | 157.0 | 158.0 | 43.0 | 63.0 | 59.0x28.0 | 62.99x27.56 | 66.93x19.69 | 66.93x27.56 | 71.0x32.0 | 83.0x31.0 | 83.0x39.0 | 94.49x19.69 | 94.49x27.56 | 100.0x39.0 | 102.0x22.0 | 102.0x32.0 | 113.0x40.0 | DRILL CHART: TOP to BOTTOM | ALL UNITS ARE IN MILS | TOLERANCE | +3.0/-3.0 | +2.0/-2.0 | PLATED | NON-PLATED | QTY | 7304 | 1352 | 18 | 8 | 16 | 1 | 9 | 2 | 6 | 5 | 4
